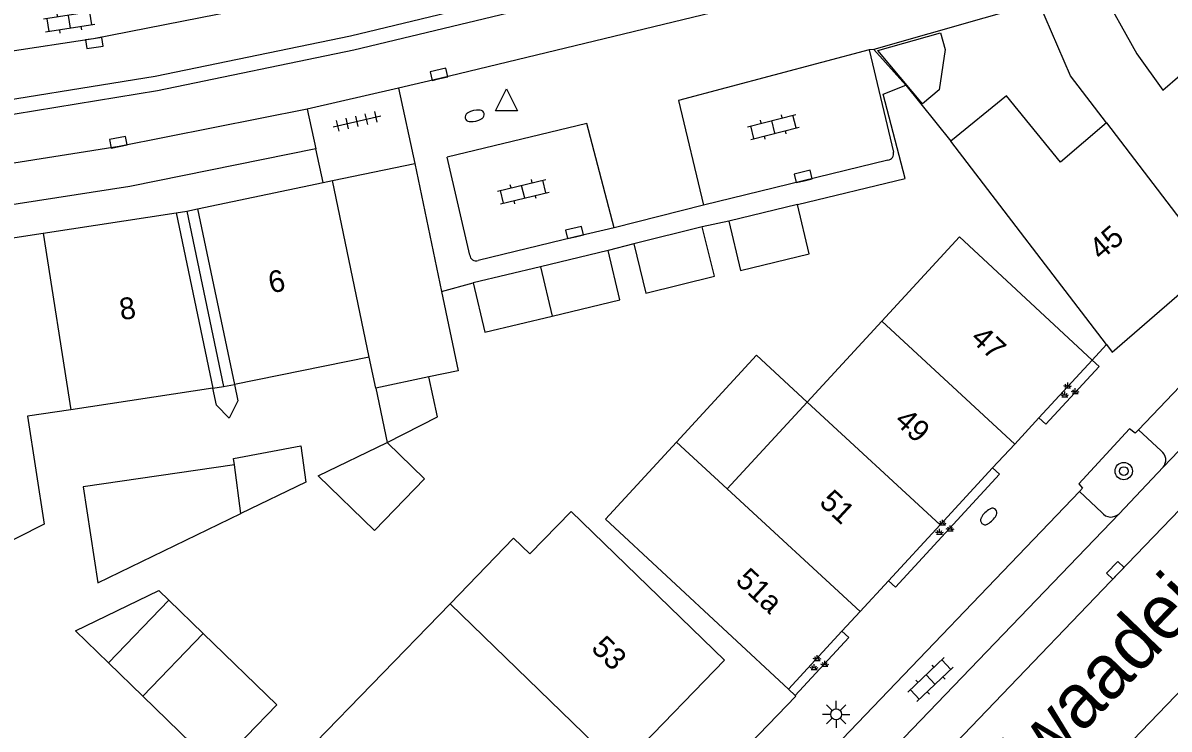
# Model space of a CAD drawing. Extents: x 132998 to 136004, y 396998 to 398512.
# Drawn here: x 133062 to 133114.7, y 397683.7 to 397716.1 of the extents above; entities that cross this region are included whole.
import ezdxf

# ---------------------------------------------------------------- set-up
doc = ezdxf.new("R2010")
doc.units = 0
for name, color, linetype in [('gg-afsc-erfafscheiding', 7, 'Continuous'), ('gg-afsc-muur', 7, 'Continuous'), ('gg-anno-huisnummerreeks BGT', 7, 'Continuous'), ('gg-anno-openbare ruimte label', 7, 'Continuous'), ('gg-bbg-bijgebouw', 7, 'Continuous'), ('gg-bbg-gedigitaliseerde bebouwing', 7, 'Continuous'), ('gg-bbg-gedigitaliseerde bebouwing onder overbouw', 7, 'Continuous'), ('gg-bbg-gedigitaliseerde bijgebouw', 7, 'Continuous'), ('gg-bbg-gedigitaliseerde overbouw', 7, 'Continuous'), ('gg-bbg-hoofdgebouw', 7, 'Continuous'), ('gg-bbg-luifel en loopbrug', 7, 'Continuous'), ('gg-bbg-pand overbouw', 7, 'Continuous'), ('gg-bbg-tussenscheiding', 7, 'Continuous'), ('gg-bbg-tussenscheiding niveau 01', 7, 'Continuous'), ('gg-knt-verharding', 7, 'Continuous'), ('gg-knt-verharding nz', 7, 'Continuous'), ('gt-grn-weggrens', 7, 'Continuous'), ('gt-symb-boom', 7, 'Continuous'), ('gt-symb-brandkraan', 7, 'Continuous'), ('gt-symb-groenvak', 7, 'Continuous'), ('gt-symb-klinker verharding', 7, 'Continuous'), ('gt-symb-kolk', 7, 'Continuous'), ('gt-symb-lichtmast', 7, 'Continuous'), ('gt-symb-tegel verharding', 7, 'Continuous'), ('gt-symb-waterafsluiter', 7, 'Continuous')]:
    doc.layers.add(name, color=color, linetype=linetype)

# ---------------------------------------------------------------- blocks, each defined once
blk = doc.blocks.new('gt0-TEG1')
at = {"layer": 'gt-symb-tegel verharding'}
for p, q in [((-1.125, 0), (1.125, 0)), ((-0.9, -0.25), (-0.9, 0.25)), ((-0.45, -0.25), (-0.45, 0.25)), ((0, -0.25), (0, 0.25)), ((0.45, -0.25), (0.45, 0.25)), ((0.9, -0.25), (0.9, 0.25))]:
    blk.add_line(p, q, dxfattribs=at)
blk = doc.blocks.new('gt0-KOLK')
at = {"layer": 'gt-symb-kolk'}
blk.add_lwpolyline([(0, 0), (0.375, 0), (0.375, 0.4), (-0.375, 0.4), (-0.375, 0), (0, 0)], dxfattribs=at)
blk = doc.blocks.new('gt0-KL1')
at = {"layer": 'gt-symb-klinker verharding'}
for p, q in [((-1.15, 0.3), (1.15, 0.3)), ((-1, -0.3), (-1, 0.3)), ((-0.5, 0.3), (-0.5, 0.45)), ((0, -0.3), (0, 0.3)), ((0.5, 0.3), (0.5, 0.45)), ((1, -0.3), (1, 0.3)), ((-1.15, -0.3), (1.15, -0.3)), ((-0.5, -0.45), (-0.5, -0.3)), ((0.5, -0.45), (0.5, -0.3))]:
    blk.add_line(p, q, dxfattribs=at)
blk = doc.blocks.new('gt0-BR')
at = {"layer": 'gt-symb-brandkraan'}
for centre, radius, start, end in [((-0.244, 0), 0.206, 107.5669, 252.4331), ((0.599, -2.664), 3, 106.892, 107.5669), ((0, -0.691), 0.938, 73.108, 106.892), ((-0.599, -2.664), 3, 72.4331, 73.108), ((0.244, 0), 0.206, 287.567, 72.4331), ((0.599, 2.664), 3, 252.4331, 253.108), ((0, 0.691), 0.938, 253.108, 286.8921), ((-0.599, 2.664), 3, 286.8921, 287.567)]:
    blk.add_arc(centre, radius, start, end, dxfattribs=at)
blk = doc.blocks.new('gt0-WAFSL')
at = {"layer": 'gt-symb-waterafsluiter'}
for p, q in [((-0.5, -0.333), (0, 0.667)), ((0, 0.667), (0.5, -0.333)), ((0.5, -0.333), (-0.5, -0.333))]:
    blk.add_line(p, q, dxfattribs=at)
blk = doc.blocks.new('gt0-BOOM')
at = {"layer": 'gt-symb-boom'}
for radius in [0.4, 0.2]:
    blk.add_circle((0, 0), radius, dxfattribs=at)
blk = doc.blocks.new('gt0-GRVAK')
at = {"layer": 'gt-symb-groenvak'}
for p, q in [((-0.11, 0.189), (-0.228, 0.24)), ((-0.182, 0.153), (0.088, 0.153)), ((-0.091, 0.211), (-0.156, 0.322)), ((-0.047, 0.214), (-0.047, 0.393)), ((-0.004, 0.211), (0.061, 0.322)), ((0.015, 0.189), (0.133, 0.24)), ((0.262, -0.052), (0.197, 0.059)), ((0.305, -0.049), (0.305, 0.13)), ((0.349, -0.052), (0.414, 0.059)), ((-0.245, -0.228), (-0.363, -0.177)), ((-0.318, -0.264), (-0.047, -0.264)), ((-0.226, -0.206), (-0.291, -0.095)), ((-0.183, -0.203), (-0.183, -0.024)), ((-0.139, -0.206), (-0.074, -0.095)), ((-0.12, -0.228), (-0.002, -0.177)), ((0.243, -0.074), (0.125, -0.023)), ((0.17, -0.11), (0.441, -0.11)), ((0.368, -0.074), (0.486, -0.023))]:
    blk.add_line(p, q, dxfattribs=at)
blk = doc.blocks.new('gt0-LMAST')
at = {"layer": 'gt-symb-lichtmast'}
for p, q in [((-0.005, 0.246), (-0.005, 0.621)), ((-0.182, 0.173), (-0.447, 0.438)), ((0.172, 0.173), (0.437, 0.438)), ((-0.255, -0.004), (-0.63, -0.004)), ((-0.182, -0.181), (-0.447, -0.446)), ((-0.005, -0.254), (-0.005, -0.629)), ((0.437, -0.446), (0.172, -0.181)), ((0.245, -0.004), (0.62, -0.004))]:
    blk.add_line(p, q, dxfattribs=at)
blk.add_circle((-0.005, -0.004), 0.25, dxfattribs=at)

msp = doc.modelspace()

# ---------------------------------------------------------------- linework, layer by layer
at = {"layer": 'gg-afsc-erfafscheiding'}
for p, q in [((133102.6, 397713.257), (133101.139, 397714.898)), ((133094.46, 397707), (133093.24, 397706.74)), ((133090.1, 397705.97), (133088.91, 397705.65))]:
    msp.add_line(p, q, dxfattribs=at)
for points in [[(133097.62, 397707.77), (133102.583, 397708.963), (133101.568, 397712.847), (133102.6, 397713.257)], [(133071.723, 397699.5), (133071.881, 397698.746), (133071.489, 397697.954), (133070.9, 397698.541), (133070.735, 397699.33)]]:
    msp.add_lwpolyline(points, dxfattribs=at)
at = {"layer": 'gg-afsc-muur'}
for p, q in [((133108.72, 397717.06), (133101.139, 397714.898)), ((133102.6, 397713.257), (133104.67, 397710.69)), ((133081.249, 397703.779), (133082.7, 397704.17))]:
    msp.add_line(p, q, dxfattribs=at)
at = {"layer": 'gg-bbg-bijgebouw'}
for p, q in [((133097.62, 397707.77), (133094.46, 397707)), ((133093.24, 397706.74), (133090.1, 397705.97)), ((133088.91, 397705.65), (133085.805, 397704.91)), ((133085.805, 397704.91), (133082.7, 397704.17))]:
    msp.add_line(p, q, dxfattribs=at)
for points in [[(133094.46, 397707), (133095.01, 397704.74), (133098.16, 397705.5), (133097.62, 397707.77)], [(133090.1, 397705.97), (133090.65, 397703.7), (133093.8, 397704.47), (133093.24, 397706.74)], [(133086.345, 397702.644), (133089.46, 397703.39), (133088.91, 397705.65)], [(133082.7, 397704.17), (133083.24, 397701.9), (133086.345, 397702.644)]]:
    msp.add_lwpolyline(points, dxfattribs=at)
at = {"layer": 'gg-bbg-gedigitaliseerde bebouwing'}
for p, q in [((133101.501, 397702.413), (133105.08, 397706.29)), ((133098.066, 397698.692), (133101.501, 397702.413)), ((133077.928, 397700.752), (133071.723, 397699.5)), ((133078.227, 397699.323), (133077.928, 397700.752)), ((133082.011, 397700.13), (133080.671, 397699.844)), ((133070.735, 397699.33), (133064.199, 397698.327)), ((133094.386, 397694.706), (133098.066, 397698.692)), ((133092.065, 397696.849), (133094.386, 397694.706))]:
    msp.add_line(p, q, dxfattribs=at)
for points in [[(133064.199, 397698.327), (133062.212, 397698.041), (133062.972, 397693.071), (133060.449, 397691.814)], [(133097.21, 397685.5), (133088.8, 397693.312), (133092.065, 397696.849)], [(133081.648, 397689.423), (133084.567, 397692.43), (133085.311, 397691.708), (133087.211, 397693.665), (133094.26, 397686.83)], [(133081.648, 397689.423), (133078.051, 397685.71), (133075.463, 397683.039)]]:
    msp.add_lwpolyline(points, dxfattribs=at)
at = {"layer": 'gg-bbg-gedigitaliseerde bebouwing onder overbouw'}
for p, q in [((133070.034, 397707.573), (133071.723, 397699.5)), ((133069.048, 397707.394), (133070.735, 397699.33))]:
    msp.add_line(p, q, dxfattribs=at)
at = {"layer": 'gg-bbg-gedigitaliseerde bijgebouw'}
for p, q in [((133065.929, 397686.709), (133068.713, 397689.581)), ((133068.713, 397689.581), (133070.293, 397688.05)), ((133067.509, 397685.178), (133070.293, 397688.05)), ((133067.509, 397685.178), (133065.929, 397686.709))]:
    msp.add_line(p, q, dxfattribs=at)
for points in [[(133101.315, 397714.844), (133104.2, 397715.667), (133104.419, 397714.898), (133104.138, 397713.036), (133103.372, 397712.393), (133101.315, 397714.844)], [(133078.227, 397699.323), (133078.747, 397696.832), (133081.062, 397698.016), (133080.671, 397699.844)], [(133071.724, 397695.806), (133071.687, 397696.102), (133074.788, 397696.674), (133075.006, 397695.016), (133072.025, 397693.57)], [(133071.724, 397695.806), (133064.767, 397694.79), (133065.449, 397690.379), (133072.025, 397693.57)]]:
    msp.add_lwpolyline(points, dxfattribs=at)
at = {"layer": 'gg-bbg-gedigitaliseerde overbouw'}
for p, q in [((133070.735, 397699.33), (133071.22, 397699.413)), ((133071.22, 397699.413), (133071.723, 397699.5))]:
    msp.add_line(p, q, dxfattribs=at)
at = {"layer": 'gg-bbg-hoofdgebouw'}
for p, q in [((133111.84, 397701.33), (133104.67, 397710.69)), ((133076.232, 397708.868), (133080.02, 397709.66)), ((133080.02, 397709.66), (133081.249, 397703.779)), ((133070.034, 397707.573), (133075.807, 397708.779)), ((133075.807, 397708.779), (133076.232, 397708.868)), ((133062.931, 397706.453), (133069.048, 397707.394)), ((133057.91, 397705.68), (133062.931, 397706.453)), ((133111.18, 397700.62), (133105.08, 397706.29)), ((133081.249, 397703.779), (133082.011, 397700.13)), ((133111.18, 397700.62), (133108.729, 397697.968)), ((133108.729, 397697.968), (133107.616, 397696.763)), ((133107.616, 397696.763), (133106.598, 397695.661)), ((133106.598, 397695.661), (133104.182, 397693.045)), ((133104.182, 397693.045), (133101.81, 397690.477)), ((133101.81, 397690.477), (133100.501, 397689.061)), ((133100.501, 397689.061), (133099.671, 397688.163)), ((133099.671, 397688.163), (133097.21, 397685.5)), ((133089.446, 397681.862), (133094.26, 397686.83))]:
    msp.add_line(p, q, dxfattribs=at)
for points in [[(133111.5, 397717.8), (133113.23, 397714.7), (133114.43, 397713.03), (133117.56, 397715.73), (133121.21, 397708.86)], [(133111.83, 397711.53), (133110.18, 397713.69), (133108.72, 397717.06)], [(133111.83, 397711.53), (133109.72, 397709.72), (133107.23, 397712.77), (133104.67, 397710.69)], [(133111.84, 397701.33), (133112.1, 397700.99), (133116.788, 397705.04)]]:
    msp.add_lwpolyline(points, dxfattribs=at)
at = {"layer": 'gg-bbg-luifel en loopbrug'}
msp.add_line((133068.251, 397690.029), (133068.713, 397689.581), dxfattribs=at)
for points in [[(133092.065, 397696.849), (133095.735, 397700.844), (133098.066, 397698.692)], [(133078.747, 397696.832), (133080.47, 397695.162), (133078.172, 397692.79), (133075.585, 397695.297), (133078.747, 397696.832)], [(133065.929, 397686.709), (133064.421, 397688.171), (133068.251, 397690.029)], [(133070.293, 397688.05), (133073.674, 397684.773), (133070.89, 397681.901), (133067.509, 397685.178)]]:
    msp.add_lwpolyline(points, dxfattribs=at)
at = {"layer": 'gg-bbg-pand overbouw'}
for p, q in [((133069.048, 397707.394), (133069.537, 397707.469)), ((133069.537, 397707.469), (133070.034, 397707.573))]:
    msp.add_line(p, q, dxfattribs=at)
at = {"layer": 'gg-bbg-tussenscheiding'}
for p, q in [((133111.83, 397711.53), (133116.788, 397705.04)), ((133077.928, 397700.752), (133076.232, 397708.868)), ((133062.931, 397706.453), (133064.199, 397698.327)), ((133085.805, 397704.91), (133086.345, 397702.644)), ((133101.501, 397702.413), (133107.616, 397696.763)), ((133080.671, 397699.844), (133078.227, 397699.323)), ((133098.066, 397698.692), (133104.182, 397693.045)), ((133072.025, 397693.57), (133071.724, 397695.806)), ((133094.386, 397694.706), (133100.501, 397689.061)), ((133081.648, 397689.423), (133089.446, 397681.862))]:
    msp.add_line(p, q, dxfattribs=at)
at = {"layer": 'gg-bbg-tussenscheiding niveau 01'}
msp.add_line((133069.537, 397707.469), (133071.22, 397699.413), dxfattribs=at)
at = {"layer": 'gg-knt-verharding'}
for p, q in [((133101.139, 397714.898), (133100.921, 397714.887)), ((133100.921, 397714.887), (133102.033, 397710.176)), ((133079.266, 397713.115), (133075.077, 397712.146)), ((133075.077, 397712.146), (133075.466, 397710.332)), ((133082.556, 397705.448), (133081.514, 397709.951)), ((133101.787, 397709.808), (133093.304, 397707.736)), ((133093.304, 397707.736), (133089.191, 397706.706)), ((133111.84, 397701.33), (133111.18, 397700.62)), ((133113.304, 397697.414), (133114.345, 397696.445)), ((133112.412, 397693.56), (133114.44, 397695.691)), ((133110.589, 397694.585), (133096.274, 397679.642)), ((133111.617, 397693.612), (133110.589, 397694.585)), ((133112.412, 397693.56), (133097.344, 397677.896)), ((133097.21, 397685.5), (133097.519, 397685.2))]:
    msp.add_line(p, q, dxfattribs=at)
for points in [[(133058.765, 397712.167), (133068.088, 397713.673), (133077.071, 397715.53), (133090.512, 397718.779), (133103.845, 397722.12), (133137.142, 397731.769), (133137.341, 397731.109), (133104.028, 397721.443), (133098.452, 397720.024), (133090.714, 397718.119), (133077.218, 397714.865), (133068.192, 397712.998), (133058.819, 397711.47)], [(133106.679, 397719.902), (133099.016, 397717.891), (133081.18, 397713.558), (133079.266, 397713.115)], [(133074.235, 397717.152), (133065.251, 397715.39), (133057.168, 397714.153), (133047.609, 397713.374)], [(133147.895, 397717.333), (133144.558, 397714.15), (133143.494, 397713.105), (133135.115, 397705.312), (133127.77, 397698.303), (133125.502, 397696.071), (133116.952, 397687.216), (133104.84, 397674.626), (133095.378, 397665.038)], [(133135.852, 397713.923), (133123.899, 397702.64), (133121.603, 397700.362), (133119.251, 397697.958), (133112.383, 397690.821), (133100.277, 397678.2), (133091.132, 397668.907), (133085.051, 397662.97), (133081.407, 397659.619), (133078.435, 397656.976), (133073.95, 397653.206), (133066.393, 397647.168), (133062.046, 397643.883)], [(133075.077, 397712.146), (133066.427, 397710.436), (133058.561, 397709.192), (133049.995, 397708.435), (133047.94, 397708.351)], [(133075.466, 397710.332), (133066.915, 397708.602), (133058.405, 397707.284), (133050.23, 397706.603), (133048.079, 397706.457), (133047.94, 397708.351)], [(133113.304, 397697.414), (133117.449, 397701.756), (133119.4, 397703.706), (133121.378, 397705.631), (133125.119, 397709.2), (133126.11, 397708.176)], [(133114.44, 397695.691), (133119.133, 397700.589), (133121.084, 397702.539), (133123.062, 397704.464), (133126.841, 397708.074)], [(133089.191, 397706.706), (133087.415, 397706.291), (133082.936, 397705.19)], [(133111.18, 397700.62), (133111.496, 397700.328), (133109.045, 397697.676), (133108.729, 397697.968)], [(133113.304, 397697.414), (133113.16, 397697.258), (133112.894, 397697.463), (133110.558, 397694.926), (133110.74, 397694.737), (133110.589, 397694.585)], [(133106.598, 397695.661), (133106.914, 397695.369), (133102.125, 397690.186), (133101.81, 397690.477)], [(133099.671, 397688.163), (133099.987, 397687.871), (133097.519, 397685.2)], [(133097.519, 397685.2), (133097.55, 397685.17), (133075.561, 397662.41), (133070.3, 397657.98)]]:
    msp.add_lwpolyline(points, dxfattribs=at)
for centre, radius, start, end in [((133101.747, 397710.101), 0.296, 277.7854, 14.6909), ((133082.842, 397705.46), 0.286, 182.4606, 289.1906), ((133114.052, 397696.025), 0.512, 319.2735, 55.0887), ((133112.038, 397693.938), 0.532, 217.7597, 314.7556)]:
    msp.add_arc(centre, radius, start, end, dxfattribs=at)
at = {"layer": 'gg-knt-verharding nz'}
for points in [[(133100.921, 397714.887), (133092.159, 397712.548), (133093.304, 397707.736)], [(133089.191, 397706.706), (133087.941, 397711.502), (133081.514, 397709.951)]]:
    msp.add_lwpolyline(points, dxfattribs=at)
at = {"layer": 'gt-grn-weggrens'}
for p, q in [((133079.266, 397713.115), (133080.02, 397709.66)), ((133075.807, 397708.779), (133075.466, 397710.332))]:
    msp.add_line(p, q, dxfattribs=at)

# ---------------------------------------------------------------- block references
at = {"layer": 'gt-symb-boom'}
msp.add_blockref('gt0-BOOM', (133112.632, 397695.519), dxfattribs=at)
at = {"layer": 'gt-symb-brandkraan'}
for p, rotation in [((133082.777, 397711.847), -166.11658196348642), ((133106.42, 397693.431), -134.69757513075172)]:
    msp.add_blockref('gt0-BR', p, dxfattribs=dict(at, rotation=rotation))
at = {"layer": 'gt-symb-groenvak'}
for p in [(133110.098, 397699.197), (133104.337, 397692.888), (133098.575, 397686.663)]:
    msp.add_blockref('gt0-GRVAK', p, dxfattribs=at)
at = {"layer": 'gt-symb-klinker verharding'}
for p, rotation in [((133064.126, 397716.168), -171.19719554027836), ((133096.514, 397711.338), 14.30027744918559), ((133085.008, 397708.36), 13.716469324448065), ((133103.747, 397685.933), -136.45841765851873)]:
    msp.add_blockref('gt0-KL1', p, dxfattribs=dict(at, rotation=rotation))
at = {"layer": 'gt-symb-kolk'}
for p, rotation in [((133065.251, 397715.39), -171.31914941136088), ((133081.18, 397713.558), 13.007504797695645), ((133066.427, 397710.436), 11.186329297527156), ((133097.932, 397708.865), 13.74462955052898), ((133087.415, 397706.291), 13.14764388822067), ((133112.383, 397690.821), 46.19265746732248)]:
    msp.add_blockref('gt0-KOLK', p, dxfattribs=dict(at, rotation=rotation))
at = {"layer": 'gt-symb-lichtmast'}
msp.add_blockref('gt0-LMAST', (133099.408, 397684.341), dxfattribs=at)
at = {"layer": 'gt-symb-tegel verharding', "rotation": 13.007504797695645}
msp.add_blockref('gt0-TEG1', (133077.362, 397711.594), dxfattribs=at)
at = {"layer": 'gt-symb-waterafsluiter'}
msp.add_blockref('gt0-WAFSL', (133084.239, 397712.415), dxfattribs=at)

# ---------------------------------------------------------------- texts
at = {"layer": 'gg-anno-huisnummerreeks BGT'}
for s, rotation, p in [('45', 40.8, (133111.583, 397705.169)), ('6', 11.8, (133073.403, 397703.68)), ('8', 8.7, (133066.512, 397702.451)), ('47', 317.2, (133105.535, 397701.551)), ('49', 317.3, (133102.038, 397697.764)), ('51', 317.2, (133098.579, 397694.021)), ('51a', 317.2, (133094.722, 397690.42)), ('53', 315.9, (133088.088, 397687.325))]:
    msp.add_text(s, height=1, rotation=rotation, dxfattribs=at).set_placement(p)
at = {"layer": 'gg-anno-openbare ruimte label'}
msp.add_text('Kwaadeindstraat', height=2.5, rotation=46.1, dxfattribs=at).set_placement((133107.466, 397680.083))

doc.saveas('drawing.dxf')
